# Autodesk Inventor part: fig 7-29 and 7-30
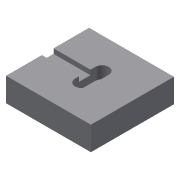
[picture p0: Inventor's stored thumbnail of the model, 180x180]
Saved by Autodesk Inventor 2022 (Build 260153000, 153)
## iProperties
Created: 2004-05
Part Number: fig 7-29 and 7-30
Document SubType Name: Modeling
Designer: CADCIM Technologies
Manufacturer: Standard
Standards Organization: Custom
Density: 1 g/cm^3
Material: Generic
Appearance: Default
Author: CADCIM Technologies
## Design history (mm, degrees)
sketch "Sketch1"
  geometry: L1 (-30.233, -25.517)-(22.302, -25.517); L2 (22.302, -25.517)-(22.302, 25.904); L3 (22.302, 25.904)-(-30.233, 25.904); L4 (-30.233, 25.904)-(-30.233, -25.517)
  constraints: 8 end point, 2 parallel, 1 horizontal, 1 perpendicular
extrude "Extrusion1" new body sketch "Sketch1" distance "d0" = 14.75; taper "d1" = 0 deg
sketch "Sketch2"
  geometry: L1 (1.047, -5.75)-(1.047, 6.846); L2 (-7.35, 6.845)-(-7.35, -5.75); A1 r 4.198 centre (-3.152, 6.846) between (1.047, 6.846) and (-7.35, 6.845); A2 r 4.198 centre (-3.152, -5.75) between (-7.35, -5.75) and (1.047, -5.75)
  constraints: 4 end point, 4 point on circle, 4 tangent, 2 centre point, 1 parallel
extrude "Extrusion2" cut sketch "Sketch2" distance "d2" = 7.5; taper "d3" = 0 deg
sketch "Sketch3"
  geometry: L1 (-7.5, 0)-(-7.5, 12.595) reference; L2 (-7.5, 0)-(0, 0) reference; L3 (-7.5, 2.416)-(-4.537, 2.416); L4 (-4.537, 2.416)-(-4.537, 9.616); L5 (-4.537, 9.616)-(-7.5, 9.616)
  constraints: 6 end point, 2 perpendicular, 2 point on line, 1 parallel
extrude "Extrusion3" cut sketch "Sketch3" extent not by distance; stored distance "d4" = 6.75; taper "d5" = 0 deg
body "Solid1"
